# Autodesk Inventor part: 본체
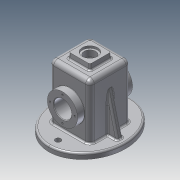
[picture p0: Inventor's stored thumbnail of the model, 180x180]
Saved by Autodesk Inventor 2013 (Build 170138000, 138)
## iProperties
Created: 2017-07
Part Number: 본체
Material: 알루미늄 6061
Document SubType Name: Modeling
Designer: Administrator
Density: 1 g/cm^3
Author: Administrator
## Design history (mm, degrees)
sketch "스케치1"
  geometry: L1 (-37, -55)-(37, -55); L2 (37, -55)-(37, 55); L3 (37, 55)-(-37, 55); L4 (-37, 55)-(-37, -55); L5 (-37, -55)-(37, 55); L6 (37, -55)-(-37, 55); 3 further points
  constraints: 12 end point, 3 midpoint, 2 parallel, 1 coincident, 1 horizontal, 1 perpendicular
  dimensions: "d0" = 74 distance of L3.end L2.end; "d1" = 110 distance of L2.end L1.end
extrude "돌출1" new body sketch "스케치1" stored distance "d2" = 74; taper "d3" = 0 deg
fillet "모깎기1" dims "d4" = 8
fillet "모깎기2" dims "d5" = 8
feature "쉘1" dims "d6" = 5
sketch "스케치2"
  geometry: L1 (-55, 32)-(47, 32) reference; L2 (-55, -29)-(-55, 29) reference; L3 (-55, 29)-(-55, 32) reference; L4 (-55, 37)-(47, 37) reference; L5 (-55, 0)-(0, 0); L6 (0, 0)-(0, 37); L7 (27.5, 32)-(20.5, 25); L8 (20.5, 25)-(0, 25); L9 (0, 32)-(27.5, 32); L10 (0, 32)-(0, 25); A1 r 8 centre (47, 29) between (55, 29) and (47, 37) reference; 1 further point
  constraints: 12 end point, 5 point on line, 2 perpendicular, 1 collinear, 1 midpoint, 1 parallel
  dimensions: "d10" = 55 distance of L5.start L5.end; "d11" = 7 distance between parallel lines of L8 L9; "d12" = 135 deg angle of L8 L7; "d136" = 55 diameter of L7.start L6
revolve "회전1" sketch "스케치2" stored, may be unused: angle "d14" = 90 deg
fillet "모깎기5" dims "d45" = 0.5
sketch "스케치7"
  geometry: C1 r 27.5 at (0, 0); 1 further point
  constraints: 1 centre point, 1 coincident
  dimensions: "d46" = 55 diameter of C1
extrude "돌출5" join sketch "스케치7" distance "d47" = 13; taper "d48" = 0 deg
sketch "스케치8"
  geometry: C1 r 27.5 at (0, 0) reference; C2 r 16 at (0, 0)
  constraints: 1 centre point, 1 coincident
  dimensions: "d49" = 32 diameter of C2
extrude "돌출6" cut sketch "스케치8" stored distance "d50" = 13; taper "d51" = 0 deg
fillet "모깎기6" dims "d52" = 0.5
sketch "스케치9"
  geometry: L1 (0, 0)-(0, 22.5); C1 r 27.5 at (0, 0) reference; 1 further point
  constraints: 2 end point, 1 coincident, 1 vertical
  dimensions: "d53" = 22.5 distance of L1.start L1.end
hole "구멍2" sketch "스케치9" at (0, 22.5) diameter "d54" = 3.242; stored, may be unused: countersink angle "d58" = 90 deg, drill point angle "d60" = 118 deg; dims "d55" = 8, "d56" = 4, "d57" = 2, "d59" = 10
node "작업 평면2"
sketch "스케치10" dims "d67" = 65, "d68" = 75
  geometry: L1 (-65, 75)-(65, 75); L2 (65, 75)-(65, -75); L3 (65, -75)-(-65, -75); L4 (-65, -75)-(-65, 75); L5 (-65, 75)-(65, -75); L6 (65, 75)-(-65, -75); L7 (-32, 29)-(-32, -29) reference; L8 (29, 32)-(-29, 32) reference; L9 (32, -29)-(32, 29) reference; L10 (29, 32)-(-29, 32) reference; L11 (-32, 29)-(-32, -29) reference; L12 (-29, -32)-(29, -32) reference; L13 (-29, -37)-(29, -37) reference; L14 (-37, -29)-(-37, 29) reference; L15 (29, 37)-(-29, 37) reference; L16 (37, 29)-(37, -29) reference; A1 r 3 centre (-29, 29) between (-29, 32) and (-32, 29) reference; A2 r 3 centre (29, -29) between (29, -32) and (32, -29) reference; A3 r 3 centre (29, 29) between (32, 29) and (29, 32) reference; A4 r 3 centre (-29, 29) between (-29, 32) and (-32, 29) reference; A5 r 3 centre (-29, -29) between (-32, -29) and (-29, -32) reference; A6 r 8 centre (29, -29) between (29, -37) and (37, -29) reference; A7 r 8 centre (-29, -29) between (-37, -29) and (-29, -37) reference; A8 r 8 centre (-29, 29) between (-29, 37) and (-37, 29) reference; A9 r 8 centre (29, 29) between (37, 29) and (29, 37) reference; 4 further points; 1 other entity
  constraints: 12 end point, 3 midpoint, 2 coincident, 2 parallel, 1 horizontal, 1 perpendicular, 1 vertical, 2 other
  dimensions: "d65" = 130 distance of L2.end L3.end; "d66" = 150 distance of L1.end L2.end
extrude "돌출7" join sketch "스케치10" distance "d69" = 10; taper "d70" = 0 deg
sketch "스케치11"
  geometry: C1 r 27.5 at (0, 0); 1 further point
  constraints: 1 centre point, 1 coincident
  dimensions: "d71" = 55 diameter of C1
extrude "돌출8" join sketch "스케치11" distance "d72" = 13; taper "d73" = 0 deg
sketch "스케치12"
  geometry: C1 r 27.5 at (0, 0) reference; C2 r 16 at (0, 0)
  constraints: 1 centre point, 1 coincident
  dimensions: "d74" = 32 diameter of C2
extrude "돌출9" cut sketch "스케치12" stored distance "d75" = 13; taper "d76" = 0 deg
sketch "스케치13"
  geometry: L1 (0, 0)-(0, 22.5); C1 r 16 at (0, 0) reference; 1 further point
  constraints: 2 coincident, 2 end point, 1 vertical
  dimensions: "d77" = 22.5 distance of L1.start L1.end
hole "구멍3" sketch "스케치13" at (0, 22.5) diameter "d78" = 3.242; stored, may be unused: countersink angle "d82" = 90 deg, drill point angle "d84" = 118 deg; dims "d79" = 8, "d80" = 4, "d81" = 2, "d83" = 10
chamfer "모따기2" distance "d88" = 1; stored, may be unused: second distance "d89" = 2, angle "d90" = 45 deg
fillet "모깎기7" dims "d91" = 0.5
sketch "스케치14"
  geometry: L1 (65, -45)-(-65, -45) reference; L2 (-65, -55)-(65, -55) reference; L3 (-37, -45)-(-37, 47) reference; L4 (-65, -45)-(-55, -45); L5 (-55, -45)-(-37, 27.194); L6 (-29, 55)-(29, 55) reference; L7 (37, 47)-(37, -45) reference; L8 (37, -45)-(65, -45) reference; L9 (65, -45)-(65, -55) reference; L10 (65, -55)-(32, -55) reference; L11 (32, -55)-(32, 47) reference; L12 (29, 50)-(-29, 50) reference; L13 (-32, 47)-(-32, -55) reference; L14 (-32, -55)-(-65, -55) reference; L15 (-65, -55)-(-65, -45) reference; L16 (-65, -45)-(-37, -45) reference; L17 (-37, -45)-(-37, 47) reference; A1 r 8 centre (-29, 47) between (-29, 55) and (-37, 47) reference; A2 r 8 centre (29, 47) between (37, 47) and (29, 55) reference; A3 r 3 centre (29, 47) between (32, 47) and (29, 50) reference; A4 r 3 centre (-29, 47) between (-29, 50) and (-32, 47) reference; 1 further point
  constraints: 4 end point, 2 point on line
  dimensions: "d92" = 10 distance of L1.end L4.end; "d93" = 14 deg angle of L5 L15
feature "리브1" sketch "스케치14" dims "d94" = 1, "d95" = 10, "d96" = 0, "d97" = 0, "d98" = 1, "d99" = 1
fillet "모깎기8" dims "d100" = 3
fillet "모깎기9" dims "d101" = 3
fillet "모깎기10" dims "d102" = 3
fillet "모깎기11" dims "d103" = 3
fillet "모깎기12" dims "d104" = 3
fillet "모깎기13" dims "d105" = 3
sketch "스케치15"
  geometry: L1 (-40, -8)-(-40, -29) reference; L2 (0, 0)-(0, -58); C1 r 5 at (0, -58); 2 further points
  constraints: 2 coincident, 2 end point, 1 centre point, 1 parallel
  dimensions: "d106" = 58 distance of L2.start L2.end; "d107" = 10 diameter of C1
extrude "돌출10" cut sketch "스케치15" stored distance "d108" = 13; taper "d109" = 0 deg
sketch "스케치16"
  geometry: L1 (9, -49)-(49, -49); L2 (49, -49)-(49, -9); L3 (49, -9)-(9, -9); L4 (9, -9)-(9, -49); L5 (9, -49)-(49, -9); L6 (49, -49)-(9, -9); 3 further points
  constraints: 12 end point, 3 midpoint, 2 parallel, 1 coincident, 1 horizontal, 1 perpendicular
  dimensions: "d110" = 40 distance of L3.end L2.end; "d111" = 40 distance of L2.end L1.end
extrude "돌출11" join sketch "스케치16" distance "d112" = 10; taper "d113" = -5 deg
fillet "모깎기14" dims "d121" = 3
fillet "모깎기15" dims "d122" = 3
chamfer "모따기3" distance "d123" = 1; stored, may be unused: second distance "d124" = 2, angle "d125" = 45 deg
sketch "스케치18"
  geometry: L1 (56.54, -48)-(56.54, -55) reference; L2 (56.54, -55)-(-56.54, -55) reference; L3 (-56.54, -55)-(-56.54, -48) reference; L4 (-53.181, -45)-(-36.55, -45) reference; L5 (29, -42)-(-29, -42) reference; L6 (36.55, -45)-(53.181, -45) reference; L7 (-29, 47)-(-29, -42) reference; L8 (29, 47)-(-29, 47) reference; L9 (29, -42)-(29, 47) reference; L10 (16.137, 65)-(-16.137, 65) reference; L11 (37, -42)-(37, 47) reference; C1 r 16 at (0, 0) reference; C2 r 28 at (0, 0) reference; 1 further point
  constraints: 5 other
  dimensions: "d126" = 30 distance from line of point (0, 35) L10; "d127" = 37 distance from line of L11 point (0, 35)
feature "엠보싱1" sketch "스케치18" dims "d128" = 0.5, "d129" = 0
sketch "스케치19"
  geometry: C1 r 14 at (29, -29); 1 further point
  constraints: 1 centre point, 1 coincident
  dimensions: "d130" = 28 diameter of C1
extrude "돌출12" cut sketch "스케치19" distance "d131" = 4; taper "d132" = 0 deg
sketch "스케치20"
  geometry: C1 r 14 at (0, 0) reference; C2 r 10.5 at (0, 0)
  constraints: 1 centre point, 1 coincident
  dimensions: "d133" = 21 diameter of C2
extrude "돌출13" cut sketch "스케치20" stored distance "d134" = 4; taper "d135" = 0 deg
node "솔리드1"
mirror "대칭1"
pattern_circular "원형 패턴2" dims angle "d62" = 360 deg
pattern_circular "원형 패턴3" dims angle "d86" = 360 deg
mirror "대칭2"
mirror "대칭3"
node "투영된 루프1"
node "투영된 루프2"
node "절단 모서리 투영1"
node "절단 모서리 투영2"
other parameters: "d64" = -55
